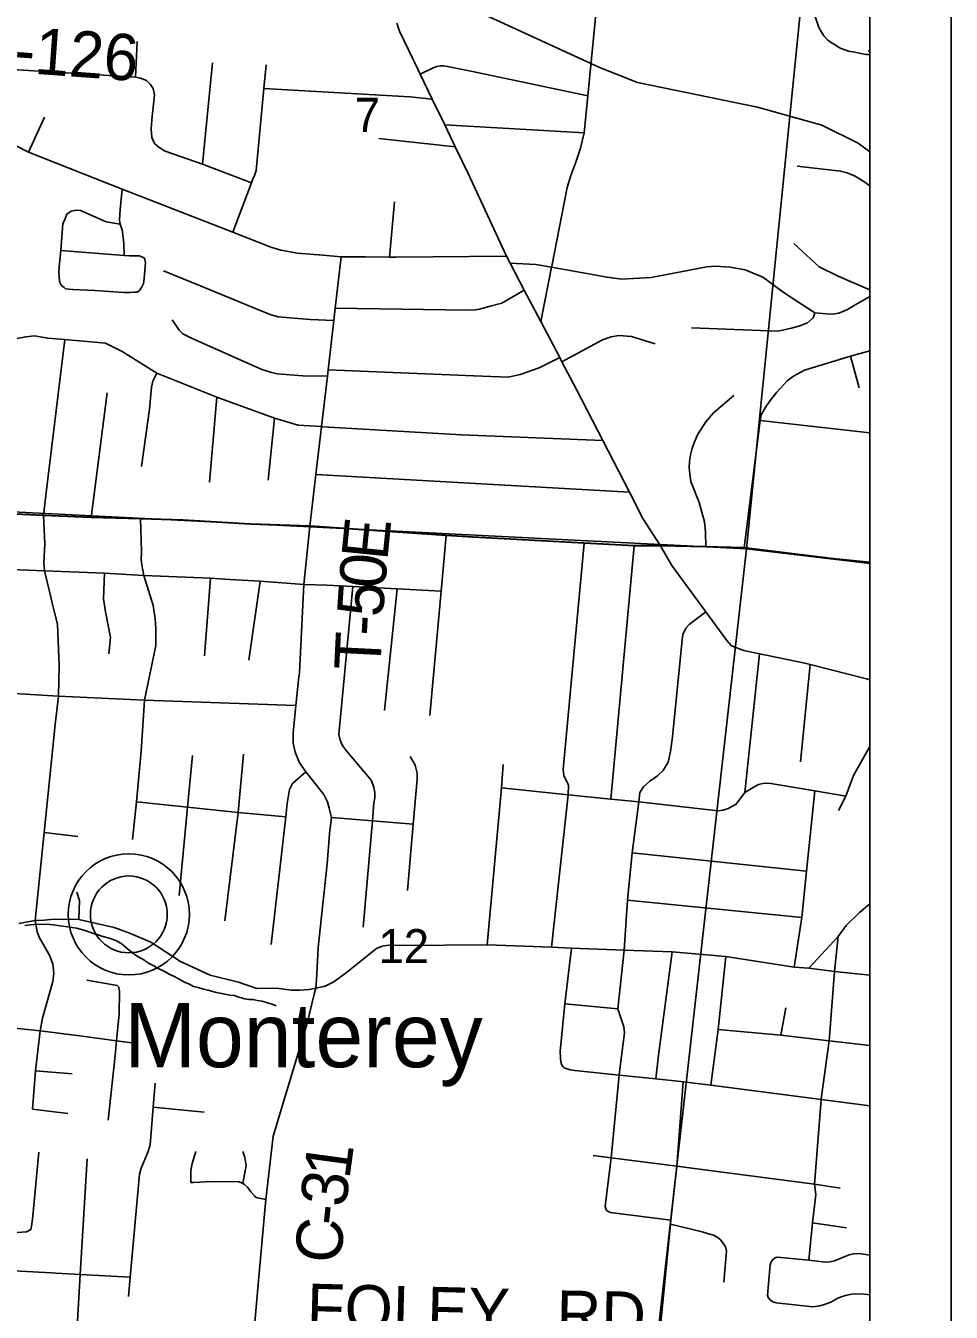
# Model space of a CAD drawing. Extents: x 0 to 34, y 0 to 22.
# Drawn here: x 7.863 to 9, y 16.255 to 17.836 of the extents above; entities that cross this region are included whole.
import ezdxf

# ---------------------------------------------------------------- set-up
doc = ezdxf.new("R2010")
doc.units = 0
for name, color, linetype in [('GM_X_City_Street', 7, 'Continuous'), ('GM_X_Corporation', 7, 'Continuous'), ('GM_X_County_Road', 7, 'Continuous'), ('GM_X_County_Road_Text', 7, 'Continuous'), ('GM_X_Minor_River', 7, 'Continuous'), ('GM_X_Rail_Line', 7, 'Continuous'), ('GM_X_Section_Text', 7, 'Continuous'), ('GM_X_State_Route', 7, 'Continuous'), ('GM_X_Township_Road', 7, 'Continuous'), ('GM_X_Township_Road_Text', 7, 'Continuous'), ('GM_X_Unincorporated', 7, 'Continuous'), ('GM_X_Unincorporated_Location', 7, 'Continuous'), ('GM_X_Unincorporated_Text', 7, 'Continuous'), ('SH_Data', 7, 'Continuous')]:
    doc.layers.add(name, color=color, linetype=linetype)

msp = doc.modelspace()

# ---------------------------------------------------------------- linework, layer by layer
at = {"layer": 'GM_X_City_Street'}
for p, q in [((8.8978, 17.8049), (8.9, 17.8047)), ((8.3349, 17.7485), (8.3626, 17.7457)), ((8.3778, 17.714), (8.549, 17.7043)), ((8.297, 17.6972), (8.3907, 17.6872)), ((8.3101, 17.5514), (8.3161, 17.6194)), ((8.2124, 17.475), (8.2416, 17.4738)), ((8.8763, 17.4296), (8.8869, 17.3908)), ((8.2037, 17.4055), (8.2337, 17.4053)), ((8.7652, 17.3508), (8.9, 17.3356)), ((8.2197, 17.2842), (8.6047, 17.2626)), ((8.5819, 16.8853), (8.6105, 17.1967)), ((8.0902, 17.1568), (8.0827, 17.0616)), ((8.3041, 16.9944), (8.3196, 17.1439)), ((8.7465, 16.8937), (8.7646, 17.0639)), ((8.8147, 16.9313), (8.8269, 17.051)), ((8.6079, 16.8193), (8.8222, 16.7971)), ((8.6025, 16.7611), (8.8164, 16.7398)), ((8.5253, 16.6339), (8.5903, 16.6276)), ((8.7905, 16.5952), (8.797, 16.6291)), ((8.8296, 16.3649), (8.8715, 16.3588))]:
    msp.add_line(p, q, dxfattribs=at)
for points in [[(8.3479, 17.7763), (8.3638, 17.7841), (8.3683, 17.7859), (8.3727, 17.7865), (8.3763, 17.7866), (8.3813, 17.7858), (8.4119, 17.7796), (8.4953, 17.7619), (8.5535, 17.7498)], [(8.9, 17.6393), (8.8928, 17.6443), (8.882, 17.6511), (8.8723, 17.655), (8.864, 17.6573), (8.8109, 17.6634)], [(8.8067, 17.5684), (8.8376, 17.5396), (8.861, 17.5283), (8.9, 17.5115)], [(8.4582, 17.5441), (8.4897, 17.5426), (8.5091, 17.5391), (8.5773, 17.5267), (8.5954, 17.5246), (8.6098, 17.5253), (8.6315, 17.5264), (8.6997, 17.5394), (8.711, 17.5403), (8.7283, 17.5391), (8.7467, 17.536), (8.7685, 17.5267), (8.7949, 17.5076), (8.8324, 17.4829)], [(8.2434, 17.4886), (8.4064, 17.4865), (8.4158, 17.4866), (8.4206, 17.4876), (8.4338, 17.4913), (8.4479, 17.495), (8.4756, 17.5108)], [(8.6809, 17.4648), (8.7869, 17.4606), (8.8038, 17.4641), (8.8142, 17.4671), (8.8235, 17.4709), (8.8302, 17.4768), (8.8324, 17.4829), (8.8464, 17.482), (8.8545, 17.4816), (8.8621, 17.4827), (8.8718, 17.4869), (8.8801, 17.4915), (8.9, 17.5031)], [(8.5219, 17.4228), (8.5717, 17.4498), (8.5821, 17.4536), (8.5918, 17.4551), (8.6071, 17.4538), (8.6362, 17.4451)], [(8.2346, 17.4131), (8.4138, 17.4058), (8.4556, 17.4041), (8.4705, 17.4074), (8.4939, 17.4153), (8.5191, 17.4282)], [(8.7457, 17.1943), (8.7652, 17.3508), (8.7665, 17.3577), (8.7713, 17.3665), (8.7776, 17.3754), (8.7859, 17.3854), (8.7983, 17.3994), (8.8062, 17.4052), (8.8196, 17.4124), (8.8763, 17.4296), (8.9, 17.4364)], [(8.6984, 17.1955), (8.6981, 17.2135), (8.6969, 17.2263), (8.6903, 17.2501), (8.6803, 17.2759), (8.6788, 17.2849), (8.6783, 17.293), (8.6787, 17.3002), (8.6796, 17.3084), (8.6819, 17.3168), (8.6852, 17.3254), (8.6885, 17.3333), (8.6987, 17.3491), (8.7081, 17.36), (8.7331, 17.3814)], [(8.1979, 17.3449), (8.2265, 17.3432), (8.2283, 17.3431), (8.3983, 17.3331), (8.5721, 17.326)], [(8.3596, 16.9884), (8.3736, 17.1412), (8.3798, 17.2095)], [(7.8867, 17.1991), (7.8855, 17.1757), (7.8862, 17.166), (7.8925, 17.1405), (7.8983, 17.1166), (7.9021, 17.1005), (7.9045, 17.0496), (7.9034, 17.0121), (7.8996, 16.9771)], [(7.9944, 16.8359), (7.9991, 16.8821), (8.005, 16.9446), (8.0093, 17.007), (8.023, 17.0744), (8.0232, 17.0875), (8.0232, 17.0952), (8.0222, 17.1074), (8.0198, 17.1236), (8.0085, 17.1604), (8.0059, 17.1735), (8.005, 17.1794), (8.0053, 17.1899)], [(8.5091, 16.7036), (8.5295, 16.8908), (8.5298, 16.9028), (8.5242, 16.9145), (8.5235, 16.9219), (8.5491, 17.2)], [(7.7363, 17.1725), (7.7606, 17.1712), (7.8358, 17.1679), (7.8862, 17.166), (7.9601, 17.163), (8.0085, 17.1604), (8.0902, 17.1568), (8.1141, 17.1555)], [(7.9601, 17.163), (7.9588, 17.1315), (7.9612, 17.1155), (7.9674, 17.084), (7.9655, 17.0641)], [(8.2332, 17.1482), (8.2651, 17.1466), (8.3196, 17.1439), (8.3736, 17.1412)], [(8.2776, 16.7281), (8.289, 16.8589), (8.2909, 16.8809), (8.2919, 16.8871), (8.2922, 16.8936), (8.2908, 16.9001), (8.2877, 16.9087), (8.257, 16.9454), (8.253, 16.9503), (8.2508, 16.9545), (8.2489, 16.9594), (8.248, 16.9647), (8.2651, 17.1466)], [(7.7811, 17.0192), (7.9034, 17.0121), (8.0093, 17.007), (8.1949, 17.0006)], [(8.8614, 16.8716), (8.8705, 16.8891), (8.8798, 16.9143), (8.9, 16.9503)], [(8.0515, 16.7672), (8.0621, 16.8755), (8.068, 16.9392)], [(8.1078, 16.7361), (8.1242, 16.8692), (8.1306, 16.9406)], [(8.332, 16.7733), (8.3393, 16.8546), (8.3442, 16.9101), (8.344, 16.9175), (8.3417, 16.9271), (8.3356, 16.938)], [(8.1646, 16.7068), (8.1827, 16.8637), (8.1843, 16.88), (8.1871, 16.8972), (8.1908, 16.9047), (8.2073, 16.9189)], [(8.4299, 16.7064), (8.4474, 16.8992), (8.4495, 16.9281)], [(8.6161, 16.8821), (8.7139, 16.8712), (8.72, 16.8719), (8.7262, 16.8738), (8.7359, 16.8791), (8.7465, 16.8937), (8.7565, 16.8996), (8.7633, 16.9034), (8.7705, 16.9051), (8.7786, 16.9048), (8.8323, 16.8956), (8.8705, 16.8891)], [(8.4474, 16.8992), (8.5295, 16.8908), (8.5819, 16.8853), (8.6161, 16.8821)], [(8.8072, 16.6789), (8.8164, 16.7398), (8.8222, 16.7971), (8.8323, 16.8956)], [(7.9991, 16.8821), (8.0621, 16.8755), (8.1242, 16.8692), (8.1827, 16.8637)], [(8.2387, 16.8628), (8.289, 16.8589), (8.3393, 16.8546)], [(8.8249, 16.3191), (8.8296, 16.3649), (8.8338, 16.3998), (8.8322, 16.4122), (8.8402, 16.5162), (8.8403, 16.5172), (8.8501, 16.5886), (8.8565, 16.6737), (8.8609, 16.7168)], [(8.637, 16.5417), (8.6404, 16.5708), (8.6571, 16.6978)], [(8.7049, 16.5338), (8.7136, 16.6024), (8.723, 16.6921)], [(8.825, 16.6779), (8.8565, 16.6737), (8.9, 16.669)], [(8.7136, 16.6024), (8.7905, 16.5952), (8.8501, 16.5886), (8.9, 16.5826)], [(8.6555, 16.3679), (8.5814, 16.3773), (8.5766, 16.3801), (8.575, 16.3848), (8.5764, 16.3984), (8.5822, 16.4446), (8.592, 16.5464)], [(8.5603, 16.4476), (8.5822, 16.4446), (8.663, 16.4343), (8.7062, 16.4285), (8.8322, 16.4122), (8.8636, 16.4072)], [(8.7207, 16.2917), (8.724, 16.3298), (8.7226, 16.3351), (8.72, 16.3399), (8.7167, 16.3437), (8.7134, 16.3467), (8.7079, 16.3495), (8.7019, 16.3513), (8.694, 16.3536), (8.6551, 16.363)], [(8.7753, 16.2729), (8.7745, 16.2761), (8.7777, 16.3132), (8.7788, 16.3168), (8.7799, 16.3186), (8.7815, 16.3205), (8.7838, 16.3219), (8.7862, 16.3226), (8.8249, 16.3191), (8.8454, 16.3165), (8.8512, 16.3169), (8.8567, 16.318), (8.8683, 16.3231), (8.8745, 16.3255), (8.88, 16.3266), (8.8873, 16.327), (8.9, 16.3251)], [(8.7753, 16.2729), (8.7775, 16.27), (8.7808, 16.2676), (8.7851, 16.2665), (8.8299, 16.2617), (8.8387, 16.2629), (8.8443, 16.2644), (8.8519, 16.2674), (8.8606, 16.2721), (8.8662, 16.2742), (8.8716, 16.2759), (8.8777, 16.2772), (8.8876, 16.2777), (8.8972, 16.2767), (8.9, 16.2762)]]:
    msp.add_lwpolyline(points, dxfattribs=at)
at = {"layer": 'GM_X_Corporation'}
for points in [[(8.9, 14.3814), (8.9, 20.9), (2.1, 20.9)], [(7.7999, 17.2384), (7.8847, 17.2346), (7.9436, 17.232), (8.0041, 17.2302), (8.0564, 17.2286), (8.139, 17.2237), (8.2121, 17.2214), (8.3796, 17.21), (8.4125, 17.2078), (8.5489, 17.2005), (8.6103, 17.1973), (8.6426, 17.1973), (8.6981, 17.196), (8.7454, 17.1948), (8.8548, 17.1813), (8.9, 17.1766), (8.9, 20.9)], [(8.9, 14.3814), (8.9, 17.1766), (8.8548, 17.1813), (8.7454, 17.1948), (8.6981, 17.196), (8.6426, 17.1973), (8.6103, 17.1973), (8.5489, 17.2005), (8.4125, 17.2078), (8.3796, 17.21), (8.2121, 17.2214), (8.139, 17.2237), (8.0564, 17.2286), (8.0041, 17.2302), (7.9436, 17.232), (7.8847, 17.2346), (7.7999, 17.2384)]]:
    msp.add_lwpolyline(points, dxfattribs=at)
for points in [[(8.8482, 18.1868), (8.7485, 17.1931), (7.7575, 17.2431), (7.8526, 18.2675)], [(8.9, 17.1752), (8.9, 18.1813), (8.8482, 18.1868), (8.7485, 17.1931)], [(7.7575, 17.2431), (8.7485, 17.1931), (8.6363, 16.199), (7.6501, 16.2281)], [(8.9, 16.1668), (8.9, 17.1752), (8.7485, 17.1931), (8.6363, 16.199)]]:
    msp.add_lwpolyline(points, close=True, dxfattribs=at)
at = {"layer": 'GM_X_County_Road'}
for p, q in [((8.2507, 17.552), (8.2804, 17.5517)), ((8.4959, 17.4722), (8.5091, 17.5391)), ((8.1491, 16.294), (8.1419, 16.2128))]:
    msp.add_line(p, q, dxfattribs=at)
for points in [[(8.5091, 17.5391), (8.5094, 17.5405), (8.5284, 17.6371), (8.5329, 17.6519), (8.5389, 17.6683), (8.5445, 17.6856), (8.549, 17.7043), (8.5535, 17.7498), (8.5802, 18.0214), (8.5891, 18.112), (8.5951, 18.1657), (8.6156, 18.3483)], [(7.6994, 17.7637), (7.7646, 17.7326), (7.8665, 17.6803), (7.9818, 17.6352), (8.1177, 17.582), (8.1642, 17.5638), (8.1766, 17.56), (8.1924, 17.5572)], [(8.1924, 17.5572), (8.1944, 17.5568), (8.1966, 17.5565), (8.2282, 17.5538), (8.2507, 17.552)], [(8.2804, 17.5517), (8.3101, 17.5514), (8.3179, 17.5513), (8.4537, 17.5525)], [(6.2065, 17.4049), (6.4191, 17.3852), (6.5024, 17.3775), (6.7305, 17.3523), (6.8403, 17.3406), (6.934, 17.3317), (7.0194, 17.3221), (7.1459, 17.3085), (7.2379, 17.2982), (7.3491, 17.2862), (7.3995, 17.2811), (7.6127, 17.2515), (7.6512, 17.2473), (7.707, 17.2464), (7.7489, 17.2402), (7.8001, 17.2379), (7.885, 17.2341), (7.9438, 17.2315), (8.0044, 17.2297), (8.0566, 17.2281), (8.1392, 17.2232), (8.1943, 17.2214)], [(8.1943, 17.2214), (8.2123, 17.2209), (8.2419, 17.2188)], [(8.2419, 17.2188), (8.3798, 17.2095), (8.4127, 17.2073), (8.5491, 17.2), (8.6105, 17.1967), (8.6429, 17.1968)], [(8.6429, 17.1968), (8.6984, 17.1955), (8.7362, 17.1945)], [(8.7362, 17.1945), (8.7457, 17.1943), (8.855, 17.1808), (8.9, 17.1761)], [(8.592, 16.5464), (8.5933, 16.5569), (8.5985, 16.5984), (8.5979, 16.6057), (8.5903, 16.6276), (8.5981, 16.7), (8.6025, 16.7611), (8.6079, 16.8193), (8.6161, 16.8821), (8.6177, 16.8937), (8.6222, 16.9005), (8.6298, 16.9074), (8.6392, 16.9139), (8.6461, 16.9207), (8.6523, 16.9307), (8.655, 16.944), (8.6575, 16.962), (8.6695, 17.0814), (8.6705, 17.0878), (8.6738, 17.0954), (8.6782, 17.1001), (8.6984, 17.1157)], [(8.1901, 16.6507), (8.2002, 16.6507), (8.2112, 16.6515), (8.2196, 16.6532), (8.2311, 16.6557), (8.2415, 16.6611), (8.2574, 16.6725), (8.2941, 16.7017), (8.301, 16.7049), (8.3087, 16.7062), (8.3249, 16.7054), (8.4299, 16.7064), (8.5091, 16.7036), (8.5335, 16.7025), (8.5981, 16.7), (8.6571, 16.6978), (8.723, 16.6921), (8.8072, 16.6789), (8.825, 16.6779), (8.8609, 16.7168), (8.8709, 16.7303), (8.8875, 16.7462), (8.9, 16.7566)], [(7.8546, 16.7325), (7.8749, 16.7362), (7.8859, 16.7369), (7.898, 16.7379), (7.9286, 16.7377), (7.972, 16.7277), (7.9918, 16.7202), (8.017, 16.7095), (8.0534, 16.6858), (8.0899, 16.6692), (8.1245, 16.6606), (8.1471, 16.6529), (8.1711, 16.6533), (8.1891, 16.6507), (8.1901, 16.6507)], [(8.5335, 16.7025), (8.5253, 16.6339), (8.5195, 16.5757), (8.5199, 16.567), (8.5201, 16.566)], [(8.5201, 16.566), (8.5205, 16.5629), (8.5217, 16.5586), (8.5234, 16.5566), (8.5247, 16.5554), (8.5271, 16.5543), (8.5295, 16.5535), (8.5321, 16.5529), (8.5375, 16.552), (8.592, 16.5464), (8.637, 16.5417), (8.6679, 16.5385), (8.6708, 16.5382)], [(8.639, 16.2005), (8.6551, 16.363), (8.6555, 16.3679), (8.663, 16.4343), (8.6708, 16.5382)], [(8.6708, 16.5382), (8.7049, 16.5338), (8.8402, 16.5162), (8.9, 16.5084)], [(8.1673, 16.4711), (8.158, 16.3933), (8.1491, 16.294)]]:
    msp.add_lwpolyline(points, dxfattribs=at)
at = {"layer": 'GM_X_Minor_River'}
for points in [[(8.8309, 17.8513), (8.8331, 17.8459), (8.8373, 17.8336), (8.8402, 17.8289), (8.8435, 17.8235), (8.8483, 17.8181), (8.8528, 17.8149), (8.8573, 17.8125), (8.8629, 17.8085), (8.8693, 17.8064), (8.8738, 17.8048), (8.8814, 17.8034), (8.8889, 17.8017), (8.8954, 17.8007), (8.9, 17.8006)], [(7.862, 16.73), (7.8688, 16.731), (7.8738, 16.7312), (7.8883, 16.7316), (7.8974, 16.7309), (7.9057, 16.7299), (7.9148, 16.7285), (7.9258, 16.7267), (7.9345, 16.7246), (7.9394, 16.7229), (7.9476, 16.72), (7.9522, 16.7187), (7.9567, 16.7171), (7.9684, 16.7137), (7.9755, 16.7109), (7.9815, 16.7073), (7.9879, 16.7021), (7.9945, 16.6966), (8.0013, 16.6918), (8.0069, 16.6886), (8.014, 16.6839), (8.0207, 16.6806), (8.0252, 16.6778), (8.0305, 16.6754), (8.0354, 16.673), (8.0402, 16.6698), (8.0459, 16.6674), (8.0519, 16.6642), (8.059, 16.6601), (8.0642, 16.6581), (8.0695, 16.6553), (8.0752, 16.654), (8.0816, 16.6519), (8.0872, 16.6506), (8.0971, 16.648), (8.1039, 16.6467), (8.1141, 16.6445), (8.1198, 16.644), (8.125, 16.6423), (8.1322, 16.6402), (8.1371, 16.6393), (8.1424, 16.6392), (8.1477, 16.6382), (8.1538, 16.6373), (8.1613, 16.6348), (8.1659, 16.6335), (8.1708, 16.6315)]]:
    msp.add_lwpolyline(points, dxfattribs=at)
at = {"layer": 'GM_X_Rail_Line'}
msp.add_lwpolyline([(8.9, 17.6811), (8.8855, 17.6915), (8.8412, 17.7137), (8.762, 17.7359), (8.6148, 17.766), (8.5673, 17.785), (8.3852, 17.869)], dxfattribs=at)
at = {"layer": 'GM_X_State_Route'}
for points in [[(8.3192, 17.8389), (8.3225, 17.8292), (8.3387, 17.7953)], [(8.3387, 17.7953), (8.3419, 17.7887), (8.3479, 17.7763), (8.3626, 17.7457), (8.3778, 17.714), (8.3907, 17.6872), (8.4066, 17.6542), (8.4537, 17.5525), (8.4582, 17.5441), (8.4756, 17.5108), (8.4959, 17.4722), (8.5191, 17.4282), (8.5219, 17.4228), (8.5398, 17.3888), (8.5721, 17.326), (8.6047, 17.2626), (8.6213, 17.2303), (8.6429, 17.1968), (8.657, 17.1724), (8.6984, 17.1157), (8.7243, 17.0802), (8.7299, 17.0738), (8.7451, 17.0679), (8.7646, 17.0639), (8.7749, 17.0618)], [(8.7749, 17.0618), (8.8203, 17.0527), (8.8269, 17.051), (8.8957, 17.0333), (8.9, 17.0319)]]:
    msp.add_lwpolyline(points, dxfattribs=at)
at = {"layer": 'GM_X_Township_Road'}
for p, q in [((7.9981, 17.7728), (8.0003, 17.8166)), ((8.0803, 17.6656), (8.0926, 17.7904)), ((8.1557, 17.7587), (8.3349, 17.7485)), ((7.8665, 17.6803), (7.8862, 17.7237)), ((8.0789, 17.5158), (8.0326, 17.5348)), ((7.9438, 17.2315), (7.9633, 17.3847)), ((8.098, 17.3795), (8.089, 17.2749)), ((8.1686, 17.3536), (8.1609, 17.2776)), ((7.8867, 17.1991), (7.885, 17.2341)), ((8.0053, 17.1899), (8.0044, 17.2297)), ((8.151, 17.1532), (8.1372, 17.0564)), ((8.205, 17.1493), (8.2332, 17.1482)), ((7.886, 16.8446), (7.9272, 16.8395)), ((7.8753, 16.5515), (7.9201, 16.5477)), ((8.0198, 16.5068), (8.0824, 16.5009))]:
    msp.add_line(p, q, dxfattribs=at)
for points in [[(8.1177, 17.582), (8.1406, 17.643), (8.1418, 17.6463), (8.1441, 17.6518), (8.1462, 17.6579), (8.1557, 17.7587), (8.1584, 17.788)], [(8.1406, 17.643), (8.0803, 17.6656), (8.0346, 17.6817), (8.027, 17.6862), (8.0213, 17.6911), (8.018, 17.6987), (8.0173, 17.7086), (8.0182, 17.7204), (8.0215, 17.751), (8.0197, 17.7588), (8.0164, 17.7637), (8.0115, 17.7684), (8.0043, 17.7716), (7.9981, 17.7728), (7.8002, 17.7851), (7.7918, 17.7827), (7.7856, 17.7784), (7.7814, 17.7709), (7.7646, 17.7326), (7.7473, 17.6987), (7.7459, 17.6894), (7.7482, 17.641), (7.7521, 17.5289)], [(7.9818, 17.6352), (7.9791, 17.6101), (7.9785, 17.5972), (7.9791, 17.5919), (7.9806, 17.5884), (7.9816, 17.5851), (7.9826, 17.579), (7.9837, 17.5683), (7.9841, 17.5537)], [(7.9791, 17.5919), (7.9619, 17.5947), (7.9306, 17.6087), (7.9254, 17.6093), (7.9191, 17.608), (7.9139, 17.6043), (7.9116, 17.5987), (7.9088, 17.5923), (7.9064, 17.5597), (7.9043, 17.5395), (7.904, 17.5324), (7.9044, 17.5276), (7.9048, 17.5219), (7.9061, 17.5187), (7.9074, 17.5164), (7.9103, 17.5141)], [(7.9064, 17.5597), (7.9841, 17.5537), (7.9909, 17.5533), (7.997, 17.5533), (8.0009, 17.5531), (8.0027, 17.5529), (8.0058, 17.552), (8.0092, 17.5503)], [(8.0092, 17.5503), (8.0105, 17.5446), (8.0093, 17.5305), (8.0088, 17.5251), (8.0077, 17.519), (8.0055, 17.5143), (8.0031, 17.5105), (8.0002, 17.5084), (7.9963, 17.5084), (7.9914, 17.5081), (7.9836, 17.5082)], [(8.2123, 17.2209), (8.2197, 17.2842), (8.2265, 17.3432), (8.2337, 17.4053), (8.2346, 17.4131), (8.2416, 17.4738), (8.2434, 17.4886), (8.2507, 17.552)], [(7.9836, 17.5082), (7.9482, 17.5107), (7.9209, 17.5117), (7.9156, 17.5121), (7.9123, 17.5125), (7.9103, 17.5141)], [(8.2124, 17.475), (8.1734, 17.4783), (8.1633, 17.4812), (8.1483, 17.4873), (8.0789, 17.5158)], [(8.2037, 17.4055), (8.1719, 17.4082), (8.1637, 17.4103), (8.1532, 17.4136), (8.067, 17.452), (8.0563, 17.4571), (8.0515, 17.4616), (8.0431, 17.4743)], [(7.8275, 17.444), (7.8488, 17.4508), (7.8635, 17.4537), (7.874, 17.4548), (7.8902, 17.4519), (7.9114, 17.4501), (7.9611, 17.4458), (7.9817, 17.4357), (8.0242, 17.409), (8.098, 17.3795), (8.1686, 17.3536), (8.1979, 17.3449)], [(7.885, 17.2341), (7.8887, 17.2655), (7.9114, 17.4501)], [(8.0242, 17.409), (8.0195, 17.3992), (8.0177, 17.3919), (8.0153, 17.3645), (8.0053, 17.2943)], [(8.1984, 17.0322), (8.1993, 17.0406), (8.205, 17.1493), (8.2123, 17.2209)], [(8.1141, 17.1555), (8.151, 17.1532), (8.205, 17.1493)], [(8.2073, 16.9189), (8.1997, 16.9301), (8.194, 16.943), (8.1916, 16.9542), (8.1917, 16.9664), (8.1949, 17.0006), (8.1984, 17.0322)], [(7.8749, 16.7362), (7.886, 16.8446), (7.8996, 16.9771)], [(8.2202, 16.6632), (8.2225, 16.7033), (8.2336, 16.8059), (8.2364, 16.8428), (8.2387, 16.8628), (8.236, 16.8742), (8.2338, 16.8821), (8.2294, 16.8912), (8.2073, 16.9189)], [(7.9286, 16.7377), (7.9293, 16.761), (7.9259, 16.7713)], [(7.9151, 16.4993), (7.8717, 16.5046), (7.8753, 16.5515), (7.8811, 16.6007), (7.8837, 16.6161), (7.8964, 16.6615), (7.8977, 16.6712), (7.8967, 16.6826), (7.8929, 16.6927), (7.8796, 16.7158), (7.8774, 16.7225), (7.8749, 16.7362)], [(7.9645, 16.4908), (7.9731, 16.5706), (7.9748, 16.5884), (7.9779, 16.6217), (7.9785, 16.6499), (7.9782, 16.6517), (7.9774, 16.6543), (7.9763, 16.6556), (7.9754, 16.6563), (7.9384, 16.663)], [(8.1673, 16.4711), (8.2086, 16.6086), (8.2181, 16.6474), (8.2196, 16.6532), (8.2202, 16.6632)], [(7.8493, 16.6038), (7.8811, 16.6007), (7.9296, 16.5944), (7.9748, 16.5884), (7.9997, 16.5851)], [(7.9895, 16.2741), (7.9916, 16.2979), (8.003, 16.4244), (8.0051, 16.432), (8.0136, 16.4526), (8.0161, 16.4605), (8.0198, 16.5068), (8.0223, 16.5363)], [(7.8329, 16.4548), (7.8214, 16.3547), (7.8168, 16.3152), (7.8179, 16.3117), (7.8212, 16.3086), (7.8265, 16.307), (7.8945, 16.3032), (7.9004, 16.3029)], [(7.8214, 16.3547), (7.853, 16.3531), (7.8644, 16.3539), (7.8696, 16.3565), (7.8707, 16.3633), (7.872, 16.3732), (7.8793, 16.4516)], [(7.9253, 16.2153), (7.9303, 16.3013), (7.9386, 16.4436)], [(8.0722, 16.4526), (8.0677, 16.4375), (8.0662, 16.4292), (8.0662, 16.4142), (8.0692, 16.4142), (8.091, 16.4157), (8.1248, 16.415), (8.1274, 16.4142), (8.1299, 16.413), (8.1318, 16.4118), (8.1357, 16.4087), (8.1398, 16.4028), (8.1442, 16.3981), (8.1456, 16.3965), (8.1481, 16.3954), (8.158, 16.3933)], [(8.1299, 16.413), (8.1338, 16.4353), (8.1323, 16.445), (8.1301, 16.4526)], [(7.9004, 16.3029), (7.9303, 16.3013), (7.9916, 16.2979)]]:
    msp.add_lwpolyline(points, dxfattribs=at)
at = {"layer": 'GM_X_Unincorporated'}
for radius in [0.0744, 0.0472]:
    msp.add_circle((7.9899, 16.7438), radius, dxfattribs=at)
at = {"layer": 'GM_X_Unincorporated_Location'}
msp.add_line((7.9899, 16.7438), (7.9899, 16.7438), dxfattribs=at)
at = {"layer": 'SH_Data'}
for p, q in [((9, 21), (9, 14)), ((8.9, 20.9), (8.9, 14.1))]:
    msp.add_line(p, q, dxfattribs=at)

# ---------------------------------------------------------------- texts
at = {"layer": 'GM_X_County_Road_Text'}
for s, height, rotation, p in [('C-126', 0.05682, 355.8754, (7.7931, 17.7826)), ('1', 0.0568, 82.2195, (8.2607, 16.4175)), ('3', 0.0568, 83.1235, (8.2565, 16.383)), ('-', 0.0568, 84.0882, (8.2541, 16.36)), ('C', 0.0568, 85.1584, (8.2502, 16.3138)), ('FOLEY', 0.05682, 358.5154, (8.2079, 16.2334)), ('RD', 0.05682, 359.0128, (8.5147, 16.225))]:
    msp.add_text(s, height=height, rotation=rotation, dxfattribs=at).set_placement(p)
at = {"layer": 'GM_X_Section_Text'}
for s, height, p in [('7', 0.0419, (8.2673, 17.7054)), ('12', 0.04186, (8.2964, 16.6839))]:
    msp.add_text(s, height=height, rotation=0, dxfattribs=at).set_placement(p)
at = {"layer": 'GM_X_Township_Road_Text'}
for s, rotation, p in [('E', 84.2303, (8.3073, 17.1776)), ('0', 85.199, (8.3044, 17.143)), ('5', 86.107, (8.302, 17.1083)), ('-', 86.8526, (8.3008, 17.0852)), ('T', 87.15, (8.2987, 17.0429))]:
    msp.add_text(s, height=0.0568, rotation=rotation, dxfattribs=at).set_placement(p)
at = {"layer": 'GM_X_Unincorporated_Text'}
msp.add_text('Monterey', height=0.07898, rotation=0, dxfattribs=at).set_placement((7.9843, 16.556))

doc.saveas('drawing.dxf')
